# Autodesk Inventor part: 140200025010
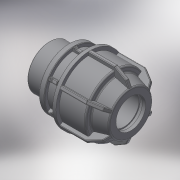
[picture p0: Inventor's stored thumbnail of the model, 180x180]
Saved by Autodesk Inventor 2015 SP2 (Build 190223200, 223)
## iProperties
Created: 2017-08
Part Number: 140200025010
Material: Generic
Description: PLASSON L.14 MALE ADAPTOR (SILVER) 25-1''
Document SubType Name: Modeling
Designer: KIM
Density: 1 g/cm^3
Appearance: Default
Author: KIM
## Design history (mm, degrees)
derived "140200.ipt"
feature "Solid1::140200.ipt"
tag "TaggingFeature1"
body "Solid1"
other parameters: "d1" = 25, "d4" = 15 deg, "d5" = 33, "d6" = 10.89, "d16" = 25.5, "d17" = 2.5, "d18" = 77, "d19" = 5.4, "d21" = 5.4, "d22" = 39.8988, "d24" = 2.5, "d25" = 45, "d26" = 37.5, "d27" = 2.5, "d28" = 135 deg, "d29" = 1.5, "d31" = 1.25, "d44" = 0.5, "d45" = 0.75, "d46" = 150 deg, "d49" = 2.5, "d50" = 0, "d51" = 1.5, "d52" = 1, "d53" = 45 deg, "d54" = 21, "d55" = 8.4, "d56" = 2.5, "d57" = 0, "d58" = 0.75, "d59" = 0.5, "d61" = 360 deg, "d63" = 33.249, "d65" = 18, "d66" = 44.88615, "d_" = 25, "R_" = 33.249, "H_" = 77, "l_2" = 18
